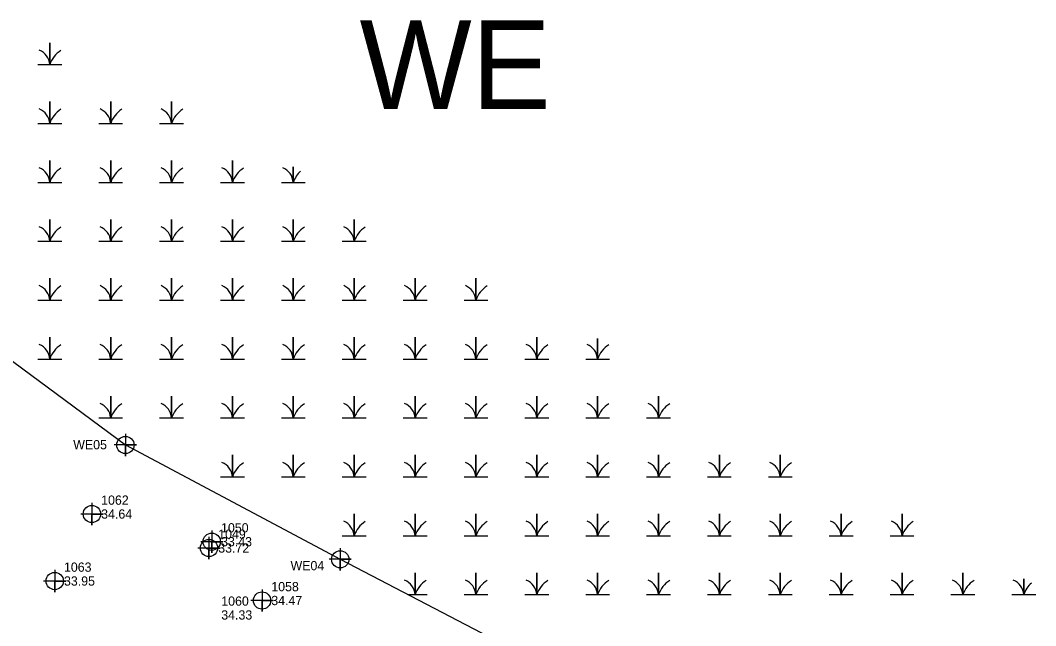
# Model space of a CAD drawing. Extents: x 2138832 to 2141061, y 149156 to 150675.
# Drawn here: x 2140787 to 2141061.5, y 149304.7 to 149468.3 of the extents above; entities that cross this region are included whole.
import ezdxf

# ---------------------------------------------------------------- set-up
doc = ezdxf.new("R2010")
doc.units = 0
for name, color, linetype in [('Default', 7, 'Continuous'), ('Exist Environmental Wetland Boundary', 7, 'Continuous'), ('Exist Environmental Wetland Boundary Cogo Number', 7, 'Continuous'), ('Exist Environmental Wetland Boundary Cogo Point CELL', 7, 'Continuous'), ('Exist Property Iron Pin Cogo Elevation', 7, 'Continuous'), ('Exist Property Iron Pin Cogo Number', 7, 'Continuous'), ('Exist Roads EOP Cogo Elevation', 7, 'Continuous'), ('Exist Roads EOP Cogo Number', 7, 'Continuous'), ('Exist Roads EOP Cogo Point CELL', 7, 'Continuous'), ('Exist Utilities Telephone UG FO SUE LOS C Cogo Elevation', 7, 'Continuous'), ('Exist Utilities Telephone UG FO SUE LOS C Cogo Number', 7, 'Continuous'), ('Exist Utilities Telephone UG FO SUE LOS C Cogo Point CELL', 7, 'Continuous')]:
    doc.layers.add(name, color=color, linetype=linetype)

msp = doc.modelspace()

# ---------------------------------------------------------------- linework, layer by layer
at = {"layer": 'Exist Environmental Wetland Boundary'}
msp.add_lwpolyline([(2140626.92, 149434.6), (2140640.09, 149441.77), (2140665.85, 149433.31), (2140691.67, 149415.77), (2140722.53, 149397.21), (2140775.79, 149382.91), (2140815.44, 149353.55), (2140873.49, 149322.65), (2140932.75, 149291.76), (2140974.9, 149268.42), (2141022.6, 149236.76)], dxfattribs=at)
at = {"layer": 'Exist Environmental Wetland Boundary Cogo Point CELL'}
for points in [[(2140791.79, 149456.36), (2140795.01, 149456.36), (2140795.01, 149462.28), (2140795.01, 149456.36), (2140798.24, 149456.36)], [(2140791.79, 149440.44), (2140795.01, 149440.44), (2140795.01, 149446.36), (2140795.01, 149440.44), (2140798.24, 149440.44)], [(2140808.24, 149440.44), (2140811.46, 149440.44), (2140811.46, 149446.36), (2140811.46, 149440.44), (2140814.69, 149440.44)], [(2140824.69, 149440.44), (2140827.91, 149440.44), (2140827.91, 149446.36), (2140827.91, 149440.44), (2140831.14, 149440.44)], [(2140791.79, 149424.52), (2140795.01, 149424.52), (2140795.01, 149430.44), (2140795.01, 149424.52), (2140798.24, 149424.52)], [(2140808.24, 149424.52), (2140811.46, 149424.52), (2140811.46, 149430.44), (2140811.46, 149424.52), (2140814.69, 149424.52)], [(2140824.69, 149424.52), (2140827.91, 149424.52), (2140827.91, 149430.44), (2140827.91, 149424.52), (2140831.14, 149424.52)], [(2140841.14, 149424.52), (2140844.37, 149424.52), (2140844.37, 149430.44), (2140844.37, 149424.52), (2140847.59, 149424.52)], [(2140857.59, 149424.52), (2140860.82, 149424.52), (2140860.82, 149428.7)], [(2140860.82, 149428.7), (2140860.82, 149424.52), (2140864.04, 149424.52)], [(2140791.79, 149408.61), (2140795.01, 149408.61), (2140795.01, 149414.52), (2140795.01, 149408.61), (2140798.24, 149408.61)], [(2140808.24, 149408.61), (2140811.46, 149408.61), (2140811.46, 149414.52), (2140811.46, 149408.61), (2140814.69, 149408.61)], [(2140824.69, 149408.61), (2140827.91, 149408.61), (2140827.91, 149414.52), (2140827.91, 149408.61), (2140831.14, 149408.61)], [(2140841.14, 149408.61), (2140844.37, 149408.61), (2140844.37, 149414.52), (2140844.37, 149408.61), (2140847.59, 149408.61)], [(2140857.59, 149408.61), (2140860.82, 149408.61), (2140860.82, 149414.52), (2140860.82, 149408.61), (2140864.04, 149408.61)], [(2140874.04, 149408.61), (2140877.27, 149408.61), (2140877.27, 149414.52), (2140877.27, 149408.61), (2140880.49, 149408.61)], [(2140791.79, 149392.69), (2140795.01, 149392.69), (2140795.01, 149398.61), (2140795.01, 149392.69), (2140798.24, 149392.69)], [(2140808.24, 149392.69), (2140811.46, 149392.69), (2140811.46, 149398.61), (2140811.46, 149392.69), (2140814.69, 149392.69)], [(2140824.69, 149392.69), (2140827.91, 149392.69), (2140827.91, 149398.61), (2140827.91, 149392.69), (2140831.14, 149392.69)], [(2140841.14, 149392.69), (2140844.37, 149392.69), (2140844.37, 149398.61), (2140844.37, 149392.69), (2140847.59, 149392.69)], [(2140857.59, 149392.69), (2140860.82, 149392.69), (2140860.82, 149398.61), (2140860.82, 149392.69), (2140864.04, 149392.69)], [(2140874.04, 149392.69), (2140877.27, 149392.69), (2140877.27, 149398.61), (2140877.27, 149392.69), (2140880.49, 149392.69)], [(2140890.49, 149392.69), (2140893.72, 149392.69), (2140893.72, 149398.61), (2140893.72, 149392.69), (2140896.95, 149392.69)], [(2140906.95, 149392.69), (2140910.17, 149392.69), (2140910.17, 149398.61), (2140910.17, 149392.69), (2140913.4, 149392.69)], [(2140791.79, 149376.77), (2140795.01, 149376.77), (2140795.01, 149382.69), (2140795.01, 149376.77), (2140798.24, 149376.77)], [(2140808.24, 149376.77), (2140811.46, 149376.77), (2140811.46, 149382.69), (2140811.46, 149376.77), (2140814.69, 149376.77)], [(2140824.69, 149376.77), (2140827.91, 149376.77), (2140827.91, 149382.69), (2140827.91, 149376.77), (2140831.14, 149376.77)], [(2140841.14, 149376.77), (2140844.37, 149376.77), (2140844.37, 149382.69), (2140844.37, 149376.77), (2140847.59, 149376.77)], [(2140857.59, 149376.77), (2140860.82, 149376.77), (2140860.82, 149382.69), (2140860.82, 149376.77), (2140864.04, 149376.77)], [(2140874.04, 149376.77), (2140877.27, 149376.77), (2140877.27, 149382.69), (2140877.27, 149376.77), (2140880.49, 149376.77)], [(2140890.49, 149376.77), (2140893.72, 149376.77), (2140893.72, 149382.69), (2140893.72, 149376.77), (2140896.95, 149376.77)], [(2140906.95, 149376.77), (2140910.17, 149376.77), (2140910.17, 149382.69), (2140910.17, 149376.77), (2140913.4, 149376.77)], [(2140923.4, 149376.77), (2140926.62, 149376.77), (2140926.62, 149382.69), (2140926.62, 149376.77), (2140929.85, 149376.77)], [(2140939.85, 149376.77), (2140943.07, 149376.77), (2140943.07, 149382.33)], [(2140943.07, 149382.33), (2140943.07, 149376.77), (2140946.3, 149376.77)], [(2140808.24, 149360.85), (2140811.46, 149360.85), (2140811.46, 149366.77), (2140811.46, 149360.85), (2140814.69, 149360.85)], [(2140824.69, 149360.85), (2140827.91, 149360.85), (2140827.91, 149366.77), (2140827.91, 149360.85), (2140831.14, 149360.85)], [(2140841.14, 149360.85), (2140844.37, 149360.85), (2140844.37, 149366.77), (2140844.37, 149360.85), (2140847.59, 149360.85)], [(2140857.59, 149360.85), (2140860.82, 149360.85), (2140860.82, 149366.77), (2140860.82, 149360.85), (2140864.04, 149360.85)], [(2140874.04, 149360.85), (2140877.27, 149360.85), (2140877.27, 149366.77), (2140877.27, 149360.85), (2140880.49, 149360.85)], [(2140890.49, 149360.85), (2140893.72, 149360.85), (2140893.72, 149366.77), (2140893.72, 149360.85), (2140896.95, 149360.85)], [(2140906.95, 149360.85), (2140910.17, 149360.85), (2140910.17, 149366.77), (2140910.17, 149360.85), (2140913.4, 149360.85)], [(2140923.4, 149360.85), (2140926.62, 149360.85), (2140926.62, 149366.77), (2140926.62, 149360.85), (2140929.85, 149360.85)], [(2140939.85, 149360.85), (2140943.07, 149360.85), (2140943.07, 149366.77), (2140943.07, 149360.85), (2140946.3, 149360.85)], [(2140956.3, 149360.85), (2140959.52, 149360.85), (2140959.52, 149366.77), (2140959.52, 149360.85), (2140962.75, 149360.85)], [(2140815.44, 149356.55), (2140815.44, 149350.55), (2140815.44, 149353.55), (2140818.44, 149353.55), (2140812.44, 149353.55)], [(2140841.14, 149344.94), (2140844.37, 149344.94), (2140844.37, 149350.85), (2140844.37, 149344.94), (2140847.59, 149344.94)], [(2140857.59, 149344.94), (2140860.82, 149344.94), (2140860.82, 149350.85), (2140860.82, 149344.94), (2140864.04, 149344.94)], [(2140874.04, 149344.94), (2140877.27, 149344.94), (2140877.27, 149350.85), (2140877.27, 149344.94), (2140880.49, 149344.94)], [(2140890.49, 149344.94), (2140893.72, 149344.94), (2140893.72, 149350.85), (2140893.72, 149344.94), (2140896.95, 149344.94)], [(2140906.95, 149344.94), (2140910.17, 149344.94), (2140910.17, 149350.85), (2140910.17, 149344.94), (2140913.4, 149344.94)], [(2140923.4, 149344.94), (2140926.62, 149344.94), (2140926.62, 149350.85), (2140926.62, 149344.94), (2140929.85, 149344.94)], [(2140939.85, 149344.94), (2140943.07, 149344.94), (2140943.07, 149350.85), (2140943.07, 149344.94), (2140946.3, 149344.94)], [(2140956.3, 149344.94), (2140959.52, 149344.94), (2140959.52, 149350.85), (2140959.52, 149344.94), (2140962.75, 149344.94)], [(2140972.75, 149344.94), (2140975.98, 149344.94), (2140975.98, 149350.85), (2140975.98, 149344.94), (2140979.2, 149344.94)], [(2140989.2, 149344.94), (2140992.43, 149344.94), (2140992.43, 149350.85), (2140992.43, 149344.94), (2140995.65, 149344.94)], [(2140874.04, 149329.02), (2140877.27, 149329.02), (2140877.27, 149334.94), (2140877.27, 149329.02), (2140880.49, 149329.02)], [(2140890.49, 149329.02), (2140893.72, 149329.02), (2140893.72, 149334.94), (2140893.72, 149329.02), (2140896.95, 149329.02)], [(2140906.95, 149329.02), (2140910.17, 149329.02), (2140910.17, 149334.94), (2140910.17, 149329.02), (2140913.4, 149329.02)], [(2140923.4, 149329.02), (2140926.62, 149329.02), (2140926.62, 149334.94), (2140926.62, 149329.02), (2140929.85, 149329.02)], [(2140939.85, 149329.02), (2140943.07, 149329.02), (2140943.07, 149334.94), (2140943.07, 149329.02), (2140946.3, 149329.02)], [(2140956.3, 149329.02), (2140959.52, 149329.02), (2140959.52, 149334.94), (2140959.52, 149329.02), (2140962.75, 149329.02)], [(2140972.75, 149329.02), (2140975.98, 149329.02), (2140975.98, 149334.94), (2140975.98, 149329.02), (2140979.2, 149329.02)], [(2140989.2, 149329.02), (2140992.43, 149329.02), (2140992.43, 149334.94), (2140992.43, 149329.02), (2140995.65, 149329.02)], [(2141005.65, 149329.02), (2141008.88, 149329.02), (2141008.88, 149334.94), (2141008.88, 149329.02), (2141012.1, 149329.02)], [(2141022.1, 149329.02), (2141025.33, 149329.02), (2141025.33, 149334.94), (2141025.33, 149329.02), (2141028.55, 149329.02)], [(2140873.49, 149325.65), (2140873.49, 149319.65), (2140873.49, 149322.65), (2140876.49, 149322.65), (2140870.49, 149322.65)], [(2140891.82, 149313.1), (2140893.72, 149313.1), (2140893.72, 149319.02), (2140893.72, 149313.1), (2140896.95, 149313.1)], [(2140906.95, 149313.1), (2140910.17, 149313.1), (2140910.17, 149319.02), (2140910.17, 149313.1), (2140913.4, 149313.1)], [(2140923.4, 149313.1), (2140926.62, 149313.1), (2140926.62, 149319.02), (2140926.62, 149313.1), (2140929.85, 149313.1)], [(2140939.85, 149313.1), (2140943.07, 149313.1), (2140943.07, 149319.02), (2140943.07, 149313.1), (2140946.3, 149313.1)], [(2140956.3, 149313.1), (2140959.52, 149313.1), (2140959.52, 149319.02), (2140959.52, 149313.1), (2140962.75, 149313.1)], [(2140972.75, 149313.1), (2140975.98, 149313.1), (2140975.98, 149319.02), (2140975.98, 149313.1), (2140979.2, 149313.1)], [(2140989.2, 149313.1), (2140992.43, 149313.1), (2140992.43, 149319.02), (2140992.43, 149313.1), (2140995.65, 149313.1)], [(2141005.65, 149313.1), (2141008.88, 149313.1), (2141008.88, 149319.02), (2141008.88, 149313.1), (2141012.1, 149313.1)], [(2141022.1, 149313.1), (2141025.33, 149313.1), (2141025.33, 149319.02), (2141025.33, 149313.1), (2141028.55, 149313.1)], [(2141038.55, 149313.1), (2141041.78, 149313.1), (2141041.78, 149319.02), (2141041.78, 149313.1), (2141045.01, 149313.1)], [(2141055.01, 149313.1), (2141058.23, 149313.1), (2141058.23, 149317.42)], [(2141058.23, 149317.42), (2141058.23, 149313.1), (2141061.46, 149313.1)]]:
    msp.add_lwpolyline(points, dxfattribs=at)
for centre in [(2140815.44, 149353.55), (2140873.49, 149322.65)]:
    msp.add_circle(centre, 2.34, dxfattribs=at)
for centre, radius, start, end in [((2140790.41, 149456.03), 4.61, 4.1403, 67.535), ((2140801.85, 149454.09), 7.21, 122.1274, 161.6222), ((2140790.41, 149440.11), 4.61, 4.1403, 67.535), ((2140801.85, 149438.17), 7.21, 122.1274, 161.6222), ((2140806.86, 149440.11), 4.61, 4.1403, 67.535), ((2140818.3, 149438.17), 7.21, 122.1274, 161.6222), ((2140823.31, 149440.11), 4.61, 4.1403, 67.535), ((2140834.76, 149438.17), 7.21, 122.1274, 161.6222), ((2140790.41, 149424.19), 4.61, 4.1403, 67.535), ((2140801.85, 149422.25), 7.21, 122.1274, 161.6222), ((2140806.86, 149424.19), 4.61, 4.1403, 67.535), ((2140818.3, 149422.25), 7.21, 122.1274, 161.6222), ((2140823.31, 149424.19), 4.61, 4.1403, 67.535), ((2140834.76, 149422.25), 7.21, 122.1274, 161.6222), ((2140839.77, 149424.19), 4.61, 4.1403, 67.535), ((2140851.21, 149422.25), 7.21, 122.1274, 161.6222), ((2140856.22, 149424.19), 4.61, 4.1403, 67.535), ((2140867.66, 149422.25), 7.21, 132.3222, 161.6222), ((2140790.41, 149408.27), 4.61, 4.1403, 67.535), ((2140801.85, 149406.33), 7.21, 122.1274, 161.6222), ((2140806.86, 149408.27), 4.61, 4.1403, 67.535), ((2140818.3, 149406.33), 7.21, 122.1274, 161.6222), ((2140823.31, 149408.27), 4.61, 4.1403, 67.535), ((2140834.76, 149406.33), 7.21, 122.1274, 161.6222), ((2140839.77, 149408.27), 4.61, 4.1403, 67.535), ((2140851.21, 149406.33), 7.21, 122.1274, 161.6222), ((2140856.22, 149408.27), 4.61, 4.1403, 67.535), ((2140867.66, 149406.33), 7.21, 122.1274, 161.6222), ((2140872.67, 149408.27), 4.61, 4.1403, 67.535), ((2140884.11, 149406.33), 7.21, 122.1274, 161.6222), ((2140790.41, 149392.36), 4.61, 4.1403, 67.535), ((2140801.85, 149390.42), 7.21, 122.1274, 161.6222), ((2140806.86, 149392.36), 4.61, 4.1403, 67.535), ((2140818.3, 149390.42), 7.21, 122.1274, 161.6222), ((2140823.31, 149392.36), 4.61, 4.1403, 67.535), ((2140834.76, 149390.42), 7.21, 122.1274, 161.6222), ((2140839.77, 149392.36), 4.61, 4.1403, 67.535), ((2140851.21, 149390.42), 7.21, 122.1274, 161.6222), ((2140856.22, 149392.36), 4.61, 4.1403, 67.535), ((2140867.66, 149390.42), 7.21, 122.1274, 161.6222), ((2140872.67, 149392.36), 4.61, 4.1403, 67.535), ((2140884.11, 149390.42), 7.21, 122.1274, 161.6222), ((2140889.12, 149392.36), 4.61, 4.1403, 67.535), ((2140900.56, 149390.42), 7.21, 122.1274, 161.6222), ((2140905.57, 149392.36), 4.61, 4.1403, 67.535), ((2140917.01, 149390.42), 7.21, 122.1274, 161.6222), ((2140790.41, 149376.44), 4.61, 4.1403, 67.535), ((2140801.85, 149374.5), 7.21, 122.1274, 161.6222), ((2140806.86, 149376.44), 4.61, 4.1403, 67.535), ((2140818.3, 149374.5), 7.21, 122.1274, 161.6222), ((2140823.31, 149376.44), 4.61, 4.1403, 67.535), ((2140834.76, 149374.5), 7.21, 122.1274, 161.6222), ((2140839.77, 149376.44), 4.61, 4.1403, 67.535), ((2140851.21, 149374.5), 7.21, 122.1274, 161.6222), ((2140856.22, 149376.44), 4.61, 4.1403, 67.535), ((2140867.66, 149374.5), 7.21, 122.1274, 161.6222), ((2140872.67, 149376.44), 4.61, 4.1403, 67.535), ((2140884.11, 149374.5), 7.21, 122.1274, 161.6222), ((2140889.12, 149376.44), 4.61, 4.1403, 67.535), ((2140900.56, 149374.5), 7.21, 122.1274, 161.6222), ((2140905.57, 149376.44), 4.61, 4.1403, 67.535), ((2140917.01, 149374.5), 7.21, 122.1274, 161.6222), ((2140922.02, 149376.44), 4.61, 4.1403, 67.535), ((2140933.46, 149374.5), 7.21, 122.1274, 161.6222), ((2140938.47, 149376.44), 4.61, 4.1403, 67.535), ((2140949.91, 149374.5), 7.21, 122.1274, 161.6222), ((2140806.86, 149360.52), 4.61, 4.1403, 67.535), ((2140818.3, 149358.58), 7.21, 122.1274, 161.6222), ((2140823.31, 149360.52), 4.61, 4.1403, 67.535), ((2140834.76, 149358.58), 7.21, 122.1274, 161.6222), ((2140839.77, 149360.52), 4.61, 4.1403, 67.535), ((2140851.21, 149358.58), 7.21, 122.1274, 161.6222), ((2140856.22, 149360.52), 4.61, 4.1403, 67.535), ((2140867.66, 149358.58), 7.21, 122.1274, 161.6222), ((2140872.67, 149360.52), 4.61, 4.1403, 67.535), ((2140884.11, 149358.58), 7.21, 122.1274, 161.6222), ((2140889.12, 149360.52), 4.61, 4.1403, 67.535), ((2140900.56, 149358.58), 7.21, 122.1274, 161.6222), ((2140905.57, 149360.52), 4.61, 4.1403, 67.535), ((2140917.01, 149358.58), 7.21, 122.1274, 161.6222), ((2140922.02, 149360.52), 4.61, 4.1403, 67.535), ((2140933.46, 149358.58), 7.21, 122.1274, 161.6222), ((2140938.47, 149360.52), 4.61, 4.1403, 67.535), ((2140949.91, 149358.58), 7.21, 122.1274, 161.6222), ((2140954.92, 149360.52), 4.61, 4.1403, 67.535), ((2140966.37, 149358.58), 7.21, 122.1274, 161.6222), ((2140839.77, 149344.6), 4.61, 4.1403, 67.535), ((2140851.21, 149342.66), 7.21, 122.1274, 161.6222), ((2140856.22, 149344.6), 4.61, 4.1403, 67.535), ((2140867.66, 149342.66), 7.21, 122.1274, 161.6222), ((2140872.67, 149344.6), 4.61, 4.1403, 67.535), ((2140884.11, 149342.66), 7.21, 122.1274, 161.6222), ((2140889.12, 149344.6), 4.61, 4.1403, 67.535), ((2140900.56, 149342.66), 7.21, 122.1274, 161.6222), ((2140905.57, 149344.6), 4.61, 4.1403, 67.535), ((2140917.01, 149342.66), 7.21, 122.1274, 161.6222), ((2140922.02, 149344.6), 4.61, 4.1403, 67.535), ((2140933.46, 149342.66), 7.21, 122.1274, 161.6222), ((2140938.47, 149344.6), 4.61, 4.1403, 67.535), ((2140949.91, 149342.66), 7.21, 122.1274, 161.6222), ((2140954.92, 149344.6), 4.61, 4.1403, 67.535), ((2140966.37, 149342.66), 7.21, 122.1274, 161.6222), ((2140971.38, 149344.6), 4.61, 4.1403, 67.535), ((2140982.82, 149342.66), 7.21, 122.1274, 161.6222), ((2140987.83, 149344.6), 4.61, 4.1403, 67.535), ((2140999.27, 149342.66), 7.21, 122.1274, 161.6222), ((2140872.67, 149328.68), 4.61, 4.1403, 67.535), ((2140884.11, 149326.75), 7.21, 122.1274, 161.6222), ((2140889.12, 149328.68), 4.61, 4.1403, 67.535), ((2140900.56, 149326.75), 7.21, 122.1274, 161.6222), ((2140905.57, 149328.68), 4.61, 4.1403, 67.535), ((2140917.01, 149326.75), 7.21, 122.1274, 161.6222), ((2140922.02, 149328.68), 4.61, 4.1403, 67.535), ((2140933.46, 149326.75), 7.21, 122.1274, 161.6222), ((2140938.47, 149328.68), 4.61, 4.1403, 67.535), ((2140949.91, 149326.75), 7.21, 122.1274, 161.6222), ((2140954.92, 149328.68), 4.61, 4.1403, 67.535), ((2140966.37, 149326.75), 7.21, 122.1274, 161.6222), ((2140971.38, 149328.68), 4.61, 4.1403, 67.535), ((2140982.82, 149326.75), 7.21, 122.1274, 161.6222), ((2140987.83, 149328.68), 4.61, 4.1403, 67.535), ((2140999.27, 149326.75), 7.21, 122.1274, 161.6222), ((2141004.28, 149328.68), 4.61, 4.1403, 67.535), ((2141015.72, 149326.75), 7.21, 122.1274, 161.6222), ((2141020.73, 149328.68), 4.61, 4.1403, 67.535), ((2141032.17, 149326.75), 7.21, 122.1274, 161.6222), ((2140889.12, 149312.77), 4.61, 4.1403, 67.535), ((2140900.56, 149310.83), 7.21, 122.1274, 161.6222), ((2140905.57, 149312.77), 4.61, 4.1403, 67.535), ((2140917.01, 149310.83), 7.21, 122.1274, 161.6222), ((2140922.02, 149312.77), 4.61, 4.1403, 67.535), ((2140933.46, 149310.83), 7.21, 122.1274, 161.6222), ((2140938.47, 149312.77), 4.61, 4.1403, 67.535), ((2140949.91, 149310.83), 7.21, 122.1274, 161.6222), ((2140954.92, 149312.77), 4.61, 4.1403, 67.535), ((2140966.37, 149310.83), 7.21, 122.1274, 161.6222), ((2140971.38, 149312.77), 4.61, 4.1403, 67.535), ((2140982.82, 149310.83), 7.21, 122.1274, 161.6222), ((2140987.83, 149312.77), 4.61, 4.1403, 67.535), ((2140999.27, 149310.83), 7.21, 122.1274, 161.6222), ((2141004.28, 149312.77), 4.61, 4.1403, 67.535), ((2141015.72, 149310.83), 7.21, 122.1274, 161.6222), ((2141020.73, 149312.77), 4.61, 4.1403, 67.535), ((2141032.17, 149310.83), 7.21, 122.1274, 161.6222), ((2141037.18, 149312.77), 4.61, 4.1403, 67.535), ((2141048.62, 149310.83), 7.21, 122.1274, 161.6222), ((2141053.63, 149312.77), 4.61, 4.1403, 67.535), ((2141065.07, 149310.83), 7.21, 131.3057, 161.6222)]:
    msp.add_arc(centre, radius, start, end, dxfattribs=at)
at = {"layer": 'Exist Roads EOP Cogo Point CELL'}
for points in [[(2140806.39, 149337.9), (2140806.39, 149331.9), (2140806.39, 149334.9), (2140809.39, 149334.9), (2140803.39, 149334.9)], [(2140796.34, 149319.79), (2140796.34, 149313.79), (2140796.34, 149316.79), (2140799.34, 149316.79), (2140793.34, 149316.79)], [(2140852.37, 149314.52), (2140852.37, 149308.52), (2140852.37, 149311.52), (2140855.37, 149311.52), (2140849.37, 149311.52)]]:
    msp.add_lwpolyline(points, dxfattribs=at)
for centre in [(2140806.39, 149334.9), (2140796.34, 149316.79), (2140852.37, 149311.52)]:
    msp.add_circle(centre, 2.34, dxfattribs=at)
at = {"layer": 'Exist Utilities Telephone UG FO SUE LOS C Cogo Point CELL'}
for points in [[(2140838.79, 149330.42), (2140838.79, 149324.42), (2140838.79, 149327.42), (2140841.79, 149327.42), (2140835.79, 149327.42)], [(2140838.03, 149328.71), (2140838.03, 149322.71), (2140838.03, 149325.71), (2140841.03, 149325.71), (2140835.03, 149325.71)]]:
    msp.add_lwpolyline(points, dxfattribs=at)
for centre in [(2140838.79, 149327.42), (2140838.03, 149325.71)]:
    msp.add_circle(centre, 2.34, dxfattribs=at)

# ---------------------------------------------------------------- texts
at = {"layer": 'Default'}
msp.add_text('WE', height=24, dxfattribs=at).set_placement((2140878.73, 149444.32))
at = {"layer": 'Exist Environmental Wetland Boundary Cogo Number'}
for s, p in [('WE05', (2140801.34, 149352.38)), ('WE04', (2140860.07, 149319.69))]:
    msp.add_text(s, height=2.5, dxfattribs=at).set_placement(p)
at = {"layer": 'Exist Property Iron Pin Cogo Elevation'}
msp.add_text('34.33', height=2.5, dxfattribs=at).set_placement((2140841.35, 149306.37))
at = {"layer": 'Exist Property Iron Pin Cogo Number'}
msp.add_text('1060', height=2.5, dxfattribs=at).set_placement((2140841.35, 149310.12))
at = {"layer": 'Exist Roads EOP Cogo Elevation'}
for s, p in [('34.64', (2140808.89, 149333.65)), ('33.95', (2140798.84, 149315.54)), ('34.47', (2140854.87, 149310.27))]:
    msp.add_text(s, height=2.5, dxfattribs=at).set_placement(p)
at = {"layer": 'Exist Roads EOP Cogo Number'}
for s, p in [('1062', (2140808.89, 149337.4)), ('1063', (2140798.84, 149319.29)), ('1058', (2140854.87, 149314.02))]:
    msp.add_text(s, height=2.5, dxfattribs=at).set_placement(p)
at = {"layer": 'Exist Utilities Telephone UG FO SUE LOS C Cogo Elevation'}
for s, p in [('33.72', (2140840.53, 149324.46)), ('33.43', (2140841.29, 149326.17))]:
    msp.add_text(s, height=2.5, dxfattribs=at).set_placement(p)
at = {"layer": 'Exist Utilities Telephone UG FO SUE LOS C Cogo Number'}
for s, p in [('1050', (2140841.29, 149329.92)), ('1049', (2140840.53, 149328.21))]:
    msp.add_text(s, height=2.5, dxfattribs=at).set_placement(p)

doc.saveas('drawing.dxf')
